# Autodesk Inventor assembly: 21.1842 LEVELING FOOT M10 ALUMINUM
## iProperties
Created: 2007-03
Part Number: 21.1842 LEVELING FOOT M10 ALUMINUM
Document SubType Name: Assembly
Designer: Andy Moles
Author: Andy Moles
